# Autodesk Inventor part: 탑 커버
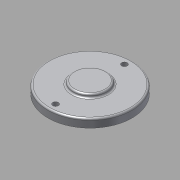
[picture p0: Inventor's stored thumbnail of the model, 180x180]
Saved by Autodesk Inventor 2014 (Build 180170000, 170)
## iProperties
Created: 2017-05
Part Number: 탑 커버
Material: 알루미늄 6061
Document SubType Name: Modeling
Designer: mduedu
Density: 1 g/cm^3
Appearance: 알루미늄 - 평지
Author: mduedu
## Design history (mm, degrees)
sketch "스케치1"
  geometry: C1 r 25 at (0, 0); 1 further point
  constraints: 1 centre point, 1 coincident
  dimensions: "d31" = 50 diameter of C1
extrude "돌출1" new body sketch "스케치1" distance "d2" = 5; taper "d3" = 0 deg
sketch "스케치2"
  geometry: C1 r 10 at (0, 0); 1 further point
  constraints: 1 centre point, 1 coincident
  dimensions: "d5" = 20 diameter of C1
extrude "돌출2" join sketch "스케치2" distance "d6" = 2; taper "d7" = 0 deg
sketch "스케치3"
  geometry: C1 r 16 at (0, 0); 1 further point
  constraints: 1 centre point, 1 coincident
  dimensions: "d32" = 32 diameter of C1
extrude "돌출3" join sketch "스케치3" distance "d10" = 3; taper "d11" = 0 deg
sketch "스케치4"
  geometry: C1 r 16 at (0, 0) reference; C2 r 14 at (0, 0); 1 further point
  constraints: 1 centre point
  dimensions: "d33" = 2 radial gap between concentric circles of C2 C1
extrude "돌출4" cut sketch "스케치4" stored distance "d14" = 2; taper "d15" = 0 deg
chamfer "모따기1" distance "d16" = 1; stored, may be unused: second distance "d17" = 2, angle "d18" = 45 deg
fillet "모깎기3" dims "d19" = 1
fillet "모깎기4" dims "d20" = 1
fillet "모깎기5" dims "d21" = 1
sketch "스케치5" dims "d34" = 41
  geometry: C1 r 25 at (0, 0) reference; 2 further points
  constraints: 2 vertical alignment, 1 coincident, 2 other
hole "구멍2" sketch "스케치5" at (0, 20.5) diameter "d35" = 3.4; stored, may be unused: countersink angle "d39" = 90 deg, drill point angle "d41" = 118 deg; dims "d36" = 6, "d37" = 4, "d38" = 2, "d40" = 8
node "솔리드1"
pattern_circular "원형 패턴1" dims angle "d43" = 360 deg
node "투영된 루프2"
